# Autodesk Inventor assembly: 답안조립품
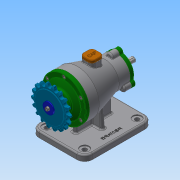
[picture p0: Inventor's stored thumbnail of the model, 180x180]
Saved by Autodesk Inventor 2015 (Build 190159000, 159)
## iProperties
Created: 2021-10
Part Number: 답안조립품
Document SubType Name: Assembly
Designer: 101256544
Author: 101256544
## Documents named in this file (16)
- C:\Users\101256544\Desktop\711006V1012\답안조립품.iam
- C:\Users\101256544\Desktop\711006V1012\본체.ipt
- C:\Users\101256544\Desktop\711006V1012\마개.ipt
- C:\Users\101256544\Desktop\711006V1012\베어링 6200.ipt
- C:\Users\101256544\Desktop\711006V1012\베어링 6203.ipt
- C:\Users\101256544\Desktop\711006V1012\볼트 M4.ipt
- 볼트 M4 x 12.ipt
- C:\Users\101256544\Desktop\711006V1012\스프로킷.ipt
- C:\Users\101256544\Desktop\711006V1012\앞커버.ipt
- C:\Users\101256544\Desktop\711006V1012\오일 실 10x20x7.ipt
- C:\Users\101256544\Desktop\711006V1012\오일 실 17x30x8.ipt
- C:\Users\101256544\Desktop\711006V1012\와셔.ipt
- C:\Users\101256544\Desktop\711006V1012\축.ipt
- C:\Users\101256544\Desktop\711006V1012\키 5x5.ipt
- 키 5 x 5.ipt
- C:\Users\101256544\Desktop\711006V1012\뒤커버.ipt
